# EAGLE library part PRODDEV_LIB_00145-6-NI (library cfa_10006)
1X6 HDR, CONN HDR BRKWAY .100 VERT
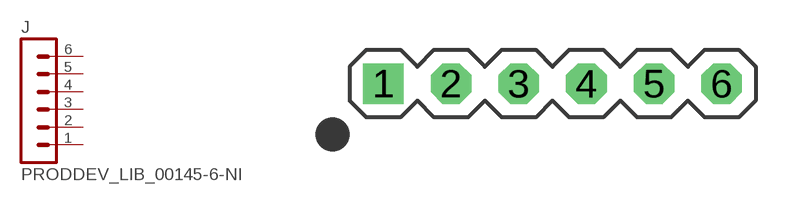
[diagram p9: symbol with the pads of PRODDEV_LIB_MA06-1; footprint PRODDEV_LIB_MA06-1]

Designator prefix J

## PRODDEV_LIB_00145-6-NI  [PRODDEV_LIB_MA06-1]
1  1  pas
2  2  pas
3  3  pas
4  4  pas
5  5  pas
6  6  pas

## Footprint PRODDEV_LIB_MA06-1 (pad centres in mm)
PIN HEADER
drill 1.016 square: 1 -6.35,0
drill 1.016 octagon: 2 -3.81,0; 3 -1.27,0; 4 1.27,0; 5 3.81,0; 6 6.35,0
